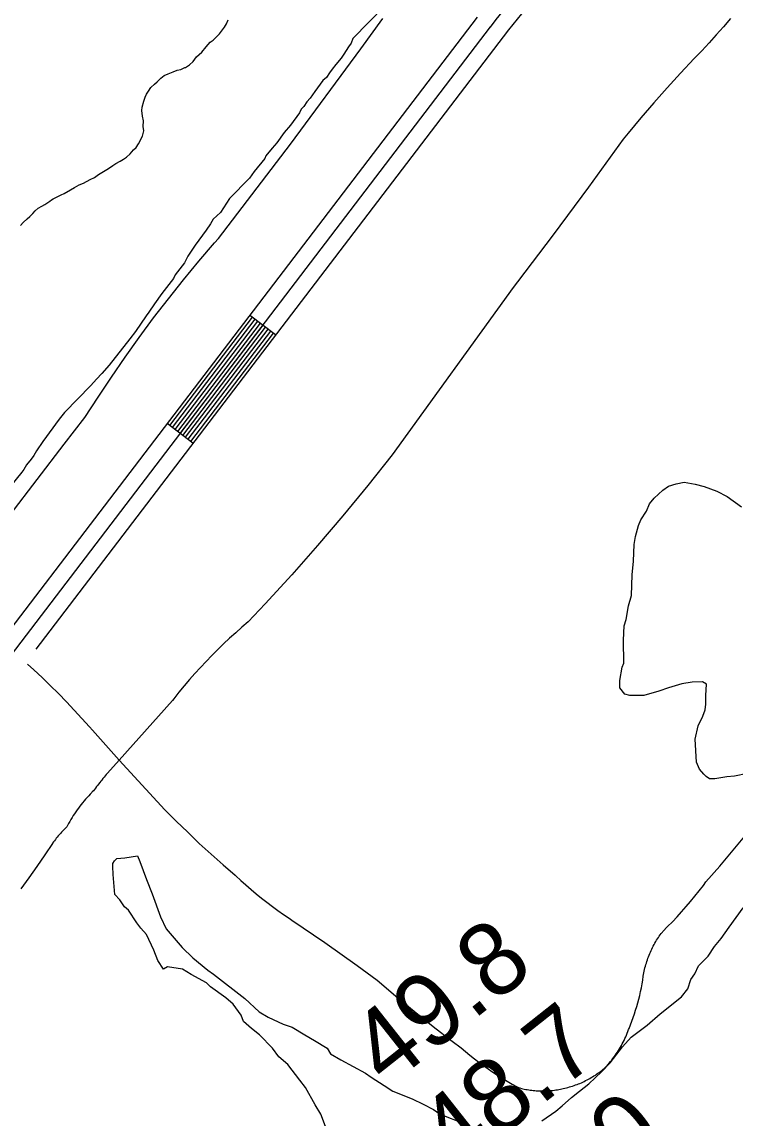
# Model space of a CAD drawing. Extents: x 3180038 to 3217926, y 922069 to 947485.
# Drawn here: x 3194643 to 3195297, y 935828 to 936834 of the extents above; entities that cross this region are included whole.
import ezdxf

# ---------------------------------------------------------------- set-up
doc = ezdxf.new("R2010")
doc.units = 0
for name, color, linetype in [('V-LEVE-TOET', 7, 'Continuous'), ('V-RIVR-RANG', 7, 'Continuous'), ('V-ROAD-CNTR', 7, 'Continuous'), ('V-SITE-VEGE', 7, 'Continuous'), ('V-TOPO-SHOR', 7, 'Continuous')]:
    doc.layers.add(name, color=color, linetype=linetype)

msp = doc.modelspace()

# ---------------------------------------------------------------- linework, layer by layer
at = {"layer": 'V-LEVE-TOET'}
for points in [[(3194632, 936381.8), (3194681.5, 936446.6), (3194700.7, 936471.1), (3194700.7, 936471.1), (3194712.7, 936489.8), (3194725, 936508.3), (3194737.6, 936526.6), (3194750.5, 936544.7), (3194763.7, 936562.5), (3194777.3, 936580.1), (3194791.1, 936597.5), (3194805.2, 936614.6), (3194819.7, 936631.5), (3194823.2, 936635.5), (3194823.2, 936635.5), (3194889.3, 936721.8), (3194953.9, 936809.3), (3194974.1, 936837.3)], [(3195293.1, 936837.2), (3195286.7, 936829.6), (3195280.1, 936822.2), (3195273.5, 936814.8), (3195266.7, 936807.6), (3195259.8, 936800.6), (3195259.8, 936800.6), (3195247.3, 936787.2), (3195235, 936773.6), (3195222.9, 936759.9), (3195210.9, 936746), (3195199.1, 936732), (3195194.6, 936726.5), (3195194.6, 936726.5), (3195162.8, 936682.5), (3195130.4, 936638.9), (3195097.5, 936595.6), (3195093.6, 936590.6), (3195093.6, 936590.6), (3194982.7, 936436.8), (3194982.7, 936436.8), (3194960.4, 936408.7), (3194937.5, 936381), (3194914.2, 936353.6), (3194890.4, 936326.7), (3194866.1, 936300.2), (3194850.5, 936283.6), (3194850.5, 936283.6), (3194844.7, 936278.7), (3194839.1, 936273.7), (3194833.4, 936268.6), (3194827.9, 936263.4), (3194822.5, 936258.2), (3194817.1, 936252.8), (3194811.8, 936247.4)], [(3194811.8, 936247.4), (3194806.7, 936241.9), (3194801.6, 936236.3), (3194796.6, 936230.7), (3194791.6, 936224.9), (3194786.8, 936219.1), (3194782.1, 936213.2), (3194780.9, 936211.6), (3194780.9, 936211.6), (3194732.2, 936156.9), (3194721.4, 936144.9), (3194721.4, 936144.9), (3194720.3, 936143.7), (3194719.3, 936142.4), (3194718.2, 936141.1), (3194717.2, 936139.9), (3194716.2, 936138.6), (3194715.2, 936137.4), (3194714.2, 936136.2), (3194713.2, 936134.9), (3194712.2, 936133.7), (3194711.2, 936132.5), (3194710.3, 936131.2), (3194709.3, 936130), (3194708.4, 936128.8), (3194707.4, 936127.6), (3194707, 936127.1), (3194707, 936127.1), (3194705.5, 936125.6), (3194704.1, 936124.1), (3194702.6, 936122.5), (3194701.2, 936121), (3194699.9, 936119.4), (3194698.5, 936117.8), (3194697.2, 936116.1), (3194695.9, 936114.5), (3194694.7, 936112.8), (3194693.4, 936111.1), (3194692.2, 936109.4), (3194691.1, 936107.7), (3194689.9, 936105.9), (3194688.8, 936104.1), (3194687.7, 936102.3), (3194686.7, 936100.5), (3194685.7, 936098.7), (3194684.7, 936096.9), (3194684.1, 936095.6), (3194684.1, 936095.6), (3194683, 936094.6), (3194682, 936093.6), (3194681, 936092.6), (3194680, 936091.6), (3194679.1, 936090.6), (3194678.1, 936089.5), (3194677.2, 936088.5), (3194676.2, 936087.4), (3194675.3, 936086.3), (3194674.4, 936085.2), (3194673.5, 936084.1), (3194672.7, 936082.9), (3194671.8, 936081.8), (3194671, 936080.6), (3194670.8, 936080.3), (3194670.8, 936080.3), (3194663.8, 936069.8), (3194656.6, 936059.3), (3194649.3, 936049), (3194641.8, 936038.9)]]:
    msp.add_lwpolyline(points, dxfattribs=at)
at = {"layer": 'V-ROAD-CNTR'}
for p, q in [((3194875.7, 936546.9), (3194851.8, 936565.1)), ((3194799.8, 936447.5), (3194776, 936465.7))]:
    msp.add_line(p, q, dxfattribs=at)
for points in [[(3195113.4, 936856.6), (3195089.3, 936826.8), (3195084.4, 936820.4), (3194655.6, 936258.5)], [(3195060.6, 936838.6), (3194276.3, 935811)], [(3195072.5, 936829.5), (3194288.5, 935802.3)], [(3194854.2, 936563.3), (3194778.4, 936463.9)], [(3194856.6, 936561.4), (3194780.8, 936462.1)], [(3194859, 936559.6), (3194783.2, 936460.3)], [(3194861.4, 936557.8), (3194785.5, 936458.4)], [(3194863.8, 936556), (3194787.9, 936456.6)], [(3194866.1, 936554.2), (3194790.3, 936454.8)], [(3194868.5, 936552.3), (3194792.7, 936453)], [(3194870.9, 936550.5), (3194795.1, 936451.2)], [(3194873.3, 936548.7), (3194797.5, 936449.3)], [(3194648, 936245), (3194653.8, 936239.7), (3194661.4, 936232.5), (3194668.9, 936225.2), (3194676.3, 936217.9), (3194683.6, 936210.4), (3194690.8, 936202.8), (3194697.9, 936195.1), (3194704.9, 936187.3), (3194707.6, 936184.2)], [(3194707.6, 936184.2), (3194732.2, 936156.9), (3194774.1, 936111.3)], [(3194774.1, 936111.3), (3194784.5, 936100.8), (3194795, 936090.6), (3194805.6, 936080.5), (3194816.4, 936070.5), (3194827.4, 936060.8), (3194838.5, 936051.2), (3194839, 936050.7)], [(3195270.6, 936045.1), (3195283.3, 936059.5), (3195295.7, 936074.2), (3195307.8, 936089), (3195319.7, 936104), (3195325.3, 936111.4)], [(3194839, 936050.7), (3194843.6, 936046.5), (3194848.3, 936042.3), (3194853.1, 936038.2), (3194857.9, 936034.2), (3194862.8, 936030.2), (3194867.7, 936026.4), (3194872.7, 936022.6), (3194877.8, 936018.9), (3194882.9, 936015.3), (3194888, 936011.7), (3194890.5, 936010.1)], [(3195231, 935999.7), (3195235.4, 936004.1), (3195239.8, 936008.5), (3195244.1, 936013.1), (3195248.3, 936017.7), (3195252.5, 936022.4), (3195256.5, 936027.1), (3195260.5, 936032), (3195264.4, 936036.9), (3195268.2, 936041.8), (3195270.6, 936045.1)], [(3194890.5, 936010.1), (3194920.7, 935989.4), (3194950.5, 935968.3), (3194968.8, 935954.9)], [(3195213.4, 935960.3), (3195213.7, 935961.8), (3195214, 935963.3), (3195214.3, 935964.8), (3195214.6, 935966.3), (3195215, 935967.8), (3195215.4, 935969.2), (3195215.9, 935970.7), (3195216.3, 935972.2), (3195216.8, 935973.6), (3195217.3, 935975.1), (3195217.8, 935976.5), (3195218.4, 935977.9), (3195219, 935979.4), (3195219.6, 935980.8), (3195220.2, 935982.2), (3195220.9, 935983.5), (3195221.6, 935984.9), (3195222.3, 935986.3), (3195223, 935987.6), (3195223.7, 935989), (3195224.5, 935990.3), (3195225.3, 935991.6), (3195226.1, 935992.9), (3195227, 935994.2), (3195227.8, 935995.4), (3195228.7, 935996.7), (3195229.6, 935997.9), (3195230.6, 935999.1), (3195231, 935999.7)], [(3194968.8, 935954.9), (3194985.7, 935940.5), (3195002.8, 935926.4), (3195020.1, 935912.5), (3195037.7, 935899), (3195046, 935892.8)], [(3195200, 935910.6), (3195201.3, 935913.9), (3195202.6, 935917.3), (3195203.8, 935920.6), (3195205, 935924), (3195206, 935927.3), (3195207.1, 935930.7), (3195208, 935934.2), (3195208.9, 935937.6), (3195209.8, 935941), (3195210.6, 935944.5), (3195211.3, 935948), (3195212, 935951.5), (3195212.6, 935955), (3195213.1, 935958.5), (3195213.4, 935960.3)], [(3195179.6, 935876.2), (3195180.8, 935877.5), (3195181.9, 935878.9), (3195183, 935880.2), (3195184.2, 935881.6), (3195185.2, 935883.1), (3195186.3, 935884.5), (3195187.3, 935885.9), (3195188.3, 935887.4), (3195189.3, 935888.9), (3195190.3, 935890.4), (3195191.2, 935891.9), (3195192.1, 935893.4), (3195193, 935895), (3195193.8, 935896.6), (3195194.7, 935898.1), (3195195.5, 935899.7), (3195196.2, 935901.3), (3195197, 935903), (3195197.7, 935904.6), (3195198.4, 935906.2), (3195199, 935907.9), (3195199.6, 935909.6), (3195200, 935910.6)], [(3195046, 935892.8), (3195050, 935889.4), (3195054, 935886.1), (3195058.1, 935882.9), (3195062.3, 935879.7), (3195066.5, 935876.6), (3195070.7, 935873.6), (3195075, 935870.7), (3195079.4, 935867.8), (3195083.8, 935865), (3195088.3, 935862.3), (3195092.8, 935859.7), (3195097.3, 935857.1), (3195098.5, 935856.5)], [(3195141.1, 935855.9), (3195142.5, 935856.2), (3195143.9, 935856.6), (3195145.3, 935857), (3195146.7, 935857.4), (3195148.1, 935857.8), (3195149.5, 935858.3), (3195150.9, 935858.8), (3195152.3, 935859.3), (3195153.6, 935859.8), (3195155, 935860.3), (3195156.3, 935860.9), (3195157.6, 935861.5), (3195158.9, 935862.1), (3195160.2, 935862.8), (3195161.5, 935863.4), (3195162.8, 935864.1), (3195164.1, 935864.8), (3195165.4, 935865.6), (3195166.6, 935866.3), (3195167.8, 935867.1), (3195169.1, 935867.9), (3195170.3, 935868.7), (3195171.4, 935869.5), (3195172.6, 935870.4), (3195173.8, 935871.3), (3195174.9, 935872.2), (3195176.1, 935873.1), (3195177.2, 935874), (3195178.3, 935875), (3195179.3, 935876), (3195179.6, 935876.2)], [(3195098.5, 935856.5), (3195099.8, 935856.1), (3195101.2, 935855.7), (3195102.5, 935855.4), (3195103.9, 935855.1), (3195105.2, 935854.8), (3195106.6, 935854.6), (3195108, 935854.3), (3195109.4, 935854.1), (3195110.7, 935853.9), (3195112.1, 935853.8), (3195113.5, 935853.6), (3195114.9, 935853.5), (3195116.3, 935853.4), (3195117.6, 935853.3), (3195119, 935853.3), (3195120.4, 935853.3), (3195121.8, 935853.3), (3195123.2, 935853.3), (3195124.6, 935853.4), (3195126, 935853.5), (3195127.4, 935853.6), (3195128.8, 935853.7), (3195130.1, 935853.8), (3195131.5, 935854), (3195132.9, 935854.2), (3195134.3, 935854.4), (3195135.6, 935854.7), (3195137, 935854.9), (3195138.3, 935855.2), (3195139.7, 935855.6), (3195141, 935855.9), (3195141.1, 935855.9)]]:
    msp.add_lwpolyline(points, dxfattribs=at)
msp.add_arc((3196814.9, 935471.1), 2209.3, 134.8468, 142.0614, dxfattribs=at)
at = {"layer": 'V-SITE-VEGE'}
for points in [[(3195533.3, 937418.1), (3194946.6, 936818.9), (3194944.9, 936814.6), (3194942.4, 936811.2), (3194938.3, 936804.4), (3194935.8, 936801), (3194930.8, 936795), (3194927.5, 936790.7), (3194925, 936787.3), (3194922.5, 936783), (3194919.1, 936780.5), (3194911.7, 936770.2), (3194907.5, 936764.3), (3194904.2, 936760.8), (3194901.7, 936756.6), (3194899.2, 936754), (3194897.5, 936750.6), (3194889.2, 936739.5), (3194883.4, 936732.7), (3194876.7, 936723.3), (3194872.6, 936718.2), (3194866.7, 936711.3), (3194865.9, 936708.8), (3194855.9, 936696.8), (3194851.8, 936690.8), (3194833.4, 936672), (3194825.1, 936659.2), (3194818.4, 936653.2), (3194815.9, 936649), (3194811.8, 936643), (3194801.8, 936629.4), (3194795.2, 936619.1), (3194791.9, 936613.2), (3194783.5, 936602.1), (3194781.9, 936598.7), (3194771.1, 936585), (3194764.4, 936575.6), (3194759.4, 936567.9), (3194756.9, 936564.5), (3194747, 936550), (3194742, 936543.2), (3194722.8, 936519.3), (3194716.2, 936511.6), (3194711.2, 936506.5), (3194706.2, 936500.5), (3194681.9, 936475.7), (3194676.9, 936469.7), (3194662, 936449.2), (3194656.2, 936440.7), (3194653.7, 936436.4), (3194651.2, 936433), (3194647, 936427.9), (3194644.5, 936423.6), (3194642.9, 936421.1), (3194631.2, 936406.6)], [(3194641.6, 936647.3), (3194643.9, 936650.1), (3194647.6, 936653.5), (3194650, 936655.6), (3194652.7, 936658.4), (3194655, 936660.8), (3194657.8, 936663.2), (3194661.1, 936665), (3194663.9, 936666.7), (3194668.6, 936669.8), (3194670, 936670.9), (3194671.6, 936671.9), (3194675.7, 936674), (3194678.8, 936675.4), (3194681.5, 936676.8), (3194687.3, 936680), (3194691, 936682.1), (3194695.4, 936684.5), (3194699.5, 936686.3), (3194705.6, 936689.4), (3194709.3, 936691.5), (3194713, 936694), (3194719.1, 936697.8), (3194722.2, 936699.5), (3194726.3, 936702.3), (3194729, 936704.1), (3194733, 936706.2), (3194736.1, 936708.2), (3194738.8, 936710), (3194742.2, 936713.1), (3194745.2, 936716.6), (3194747.6, 936719), (3194749.9, 936722.4), (3194753.6, 936729.3), (3194754.6, 936734.1), (3194754.2, 936738.2), (3194754.4, 936743.3), (3194753.4, 936747.7), (3194753, 936752.9), (3194753.3, 936755.9), (3194754.6, 936761.4), (3194755.9, 936765.2), (3194757.2, 936767.9), (3194758.9, 936770.7), (3194761.2, 936773.8), (3194764.6, 936776.9), (3194767, 936779), (3194770.3, 936782.4), (3194773.4, 936784.9), (3194777.1, 936786.6), (3194781.5, 936788.4), (3194785.3, 936789.8), (3194788.7, 936790.5), (3194792.4, 936792.3), (3194793.1, 936792.3), (3194796.5, 936794.7), (3194799.9, 936797.8), (3194803.2, 936802), (3194808, 936806.5), (3194812, 936811.3), (3194815.7, 936815.4), (3194818.4, 936817.5), (3194821.1, 936820), (3194824.1, 936823.1), (3194828.8, 936829.3), (3194830.5, 936832.4), (3194832.2, 936836.1)], [(3195308.6, 936144.5), (3195296.9, 936142.2), (3195289.7, 936141.4), (3195278.8, 936139.8), (3195273.7, 936139.7), (3195270.7, 936141.9), (3195268.5, 936144), (3195264.8, 936148.4), (3195261.8, 936154.9), (3195260.8, 936176), (3195263.6, 936188.4), (3195267.8, 936197.2), (3195270, 936203.1), (3195270.6, 936208.2), (3195270.5, 936216.2), (3195271.1, 936226.4), (3195267.5, 936228.6), (3195258, 936228.4), (3195248.5, 936226.9), (3195236.2, 936223.1), (3195227.5, 936220), (3195213.7, 936216.2), (3195200.6, 936216.1), (3195196.2, 936217.5), (3195191.7, 936223.2), (3195191.6, 936229.8), (3195193.7, 936242.2), (3195195.1, 936245.9), (3195194.8, 936267), (3195195.4, 936280.1), (3195197.5, 936286), (3195199.5, 936298.4), (3195202.3, 936307.9), (3195202.8, 936326.9), (3195204.1, 936339.3), (3195204.7, 936354.6), (3195206, 936361.9), (3195208.8, 936372.1), (3195210.9, 936377.2), (3195215.9, 936385.3), (3195218.8, 936391.9), (3195223.1, 936397.1), (3195231, 936404.5), (3195236.1, 936408.2), (3195243.3, 936410.4), (3195250.6, 936412), (3195260.8, 936409.9), (3195268.9, 936407.8), (3195280.6, 936403.6), (3195290.1, 936398.6), (3195303.3, 936389.3)], [(3194757.1, 935996.9), (3194751.9, 936002.6), (3194748.2, 936007.7), (3194740.7, 936019.3), (3194737.1, 936022.1), (3194732.6, 936028.6), (3194728.2, 936033.7), (3194726.5, 936051.9), (3194726.4, 936059.2), (3194726.4, 936062.1), (3194727.8, 936064.3), (3194730, 936066.5), (3194737.2, 936067.3), (3194748.9, 936068.9), (3194751.1, 936063.8), (3194757.2, 936047.2), (3194762.4, 936034.1), (3194770, 936013.1), (3194775.2, 936002.2), (3194790, 935984.9), (3194799.6, 935975.5), (3194813.6, 935964.1), (3194818.7, 935960.5), (3194847.4, 935938.2), (3194860.7, 935926), (3194868.8, 935921), (3194882.7, 935914.6), (3194890.8, 935911.8), (3194902.5, 935904.7), (3194911.3, 935899.7), (3194923.1, 935892.5), (3194926, 935887.5), (3194935.6, 935881.8), (3194958.3, 935869.7), (3194963.5, 935866.1), (3194975.2, 935858.2), (3194983.3, 935853.2), (3195000.9, 935846.1), (3195011.1, 935841.2), (3195020.7, 935836.2), (3195026.6, 935831.9), (3195048.5, 935823.4)], [(3195119.9, 935825.8), (3195132.9, 935834.7), (3195138.7, 935839.8), (3195147.3, 935847.2), (3195154.6, 935853.2), (3195163.2, 935859.8), (3195174.7, 935870.9), (3195182.7, 935879), (3195194.1, 935893.7), (3195202, 935902.6), (3195216.5, 935913.7), (3195228.7, 935924), (3195248.2, 935939.6), (3195254, 935946.9), (3195256.8, 935955.7), (3195260.3, 935960.9), (3195263.9, 935968.2), (3195272.5, 935977.1), (3195278.3, 935985.9), (3195284.7, 935993.2), (3195291.9, 936003.5), (3195304.8, 936021.2)], [(3194922.5, 935818.2), (3194917.3, 935832), (3194912, 935840.7), (3194903.1, 935856.6), (3194897.9, 935863.1), (3194886.8, 935877.5), (3194878.7, 935884.7), (3194872.8, 935892.6), (3194861, 935904.9), (3194853.6, 935910.6), (3194846.2, 935917.1), (3194844, 935922.9), (3194836.6, 935933), (3194829.9, 935938.7), (3194816, 935948.8), (3194812.3, 935952.4), (3194798.3, 935960.2), (3194790.2, 935965.2), (3194776.4, 935967.2), (3194772.8, 935965), (3194767.6, 935973), (3194763.8, 935982.4), (3194757.1, 935996.9)]]:
    msp.add_lwpolyline(points, dxfattribs=at)
at = {"layer": 'V-TOPO-SHOR'}
for points in [[(3194753.3, 936755.9), (3194754.6, 936761.4), (3194755.9, 936765.2), (3194757.2, 936767.9), (3194758.9, 936770.7), (3194761.2, 936773.8), (3194764.6, 936776.9), (3194767, 936779), (3194770.3, 936782.4), (3194773.4, 936784.9), (3194777.1, 936786.6), (3194781.5, 936788.4), (3194785.3, 936789.8), (3194788.7, 936790.5), (3194792.4, 936792.3), (3194793.1, 936792.3), (3194796.5, 936794.7), (3194799.9, 936797.8), (3194803.2, 936802), (3194808, 936806.5), (3194812, 936811.3), (3194815.7, 936815.4), (3194818.4, 936817.5), (3194821.1, 936820), (3194824.1, 936823.1), (3194828.8, 936829.3), (3194830.5, 936832.4), (3194832.2, 936836.1)], [(3194641.6, 936647.3), (3194643.9, 936650.1), (3194647.6, 936653.5), (3194650, 936655.6), (3194652.7, 936658.4), (3194655, 936660.8), (3194657.8, 936663.2), (3194661.1, 936665), (3194663.9, 936666.7), (3194668.6, 936669.8), (3194670, 936670.9), (3194671.6, 936671.9), (3194675.7, 936674), (3194678.8, 936675.4), (3194681.5, 936676.8), (3194687.3, 936680), (3194691, 936682.1), (3194695.4, 936684.5), (3194699.5, 936686.3), (3194705.6, 936689.4), (3194709.3, 936691.5), (3194713, 936694), (3194719.1, 936697.8), (3194722.2, 936699.5), (3194726.3, 936702.3), (3194729, 936704.1), (3194733, 936706.2), (3194736.1, 936708.2), (3194738.8, 936710), (3194742.2, 936713.1), (3194745.2, 936716.6), (3194747.6, 936719), (3194749.9, 936722.4), (3194753.6, 936729.3), (3194754.6, 936734.1), (3194754.2, 936738.2), (3194754.4, 936743.3), (3194753.4, 936747.7), (3194753, 936752.9), (3194753.3, 936755.9)]]:
    msp.add_lwpolyline(points, dxfattribs=at)

# ---------------------------------------------------------------- texts
at = {"layer": 'V-RIVR-RANG'}
for s, p in [('49.8', (3194978.1, 935855.6)), ('48.7', (3195040.3, 935777.3)), ('48.0', (3195100.3, 935697.2))]:
    msp.add_text(s, height=67, rotation=38.3283, dxfattribs=at).set_placement(p)

doc.saveas('drawing.dxf')
